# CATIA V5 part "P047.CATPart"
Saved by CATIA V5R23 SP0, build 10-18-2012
Part number: P047
Definition: Patin
Description: Patin
Bounding box of the stored display mesh (mm): x -10 to 0, y -10.992 to 10.992, z -10.984 to 10.984
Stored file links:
  C:\wamp\www\COURS\CONCEPTION GMP1\TITRE 02-SEMESTRE 2\03-TP7-PRESSE MECANIQUE\eleve\P047.CATPart
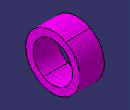
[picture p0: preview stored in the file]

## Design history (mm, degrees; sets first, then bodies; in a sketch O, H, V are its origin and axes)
Body1 (main body)
  Sketch1 on zx-plane, origin (0, 0, 0), H (-1, 0, 0), V (0, 0, 1)
    line L1 (0, 11) -> (10, 11)
    line L2 (10, 11) -> (10, 8)
    line L3 (10, 8) -> (0, 8)
    line L4 (0, 8) -> (0, 11)
    distance L3 H = 8
    distance L1 H = 11
    distance L2 L4 = 10
    horizontal: L1 H, L3 H
    vertical: L2 V, L4 V
    coincidence: L4 V
  Shaft1: profile Sketch1, axis Sketch1.H, angle 360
